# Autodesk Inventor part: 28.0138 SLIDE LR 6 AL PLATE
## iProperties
Created: 2007-06
Part Number: 28.0138 SLIDE LR 6 AL PLATE
Material: Aluminum-6061
Document SubType Name: Modeling
Designer: Andy Moles
Mass: 245.633 g
Surface Area: 233.988 cm^2
Volume: 90.6395 cm^3
Density: 2.71 g/cm^3
Author: Andy Moles
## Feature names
1. Base1
